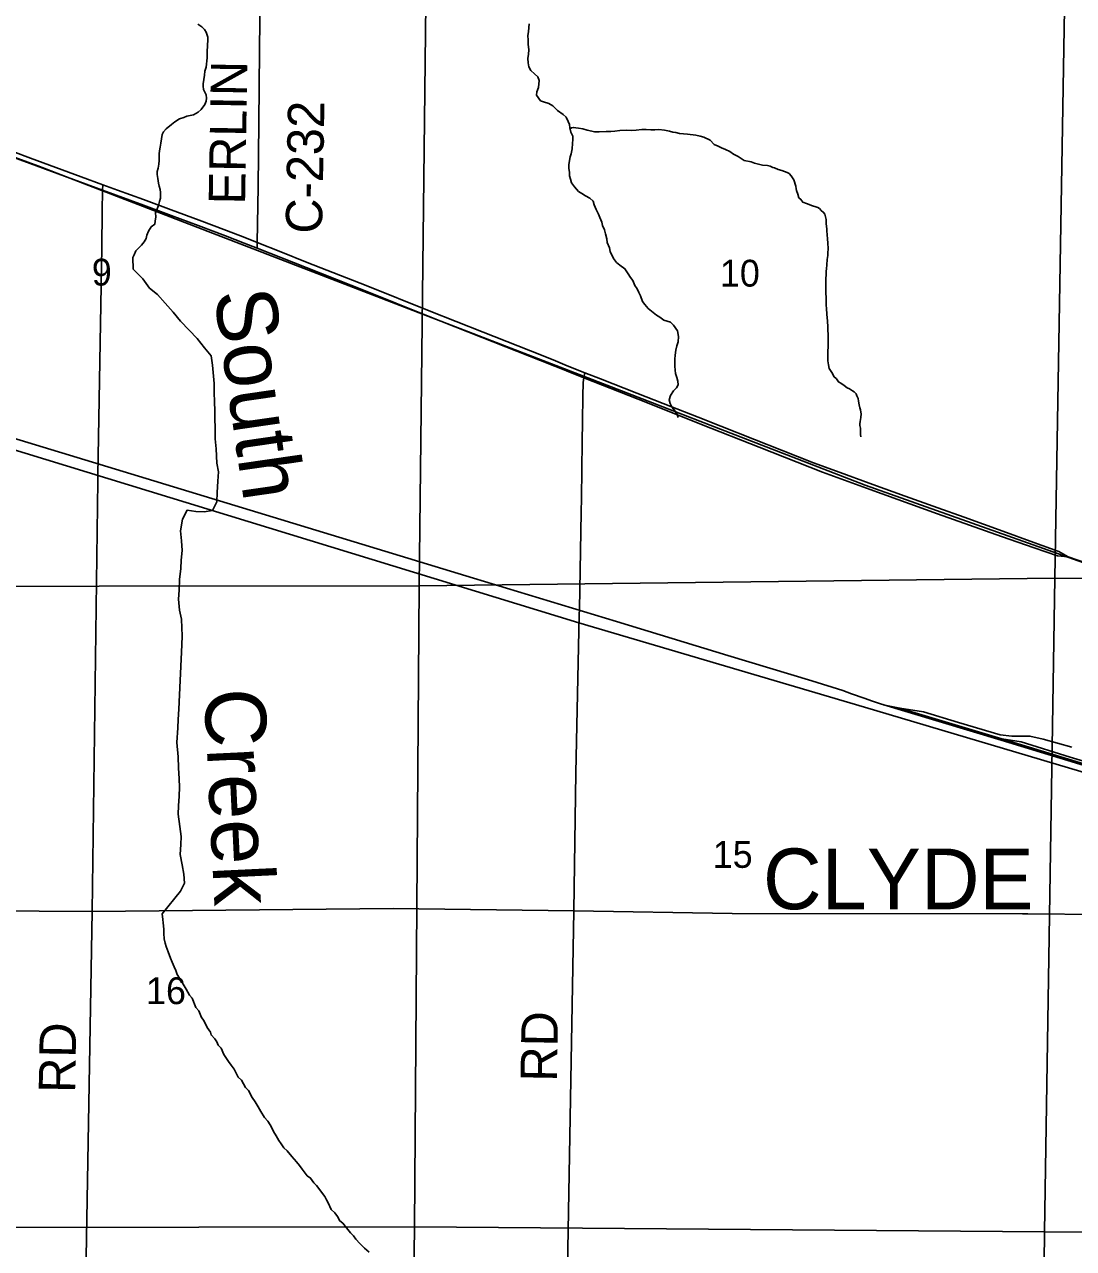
# Model space of a CAD drawing. Extents: x 0 to 34, y 0 to 22.
# Drawn here: x 4.9 to 6.537, y 17.423 to 19.332 of the extents above; entities that cross this region are included whole.
import ezdxf

# ---------------------------------------------------------------- set-up
doc = ezdxf.new("R2010")
doc.units = 0
for name, color, linetype in [('GM_X_Corporation_Text', 7, 'Continuous'), ('GM_X_County_Road', 7, 'Continuous'), ('GM_X_County_Road_Text', 7, 'Continuous'), ('GM_X_Minor_River', 7, 'Continuous'), ('GM_X_Minor_River_Text', 7, 'Continuous'), ('GM_X_Rail_Line', 7, 'Continuous'), ('GM_X_Section', 7, 'Continuous'), ('GM_X_Section_Text', 7, 'Continuous'), ('GM_X_Township_Road', 7, 'Continuous'), ('GM_X_Township_Road_Text', 7, 'Continuous'), ('GM_X_US_Route', 7, 'Continuous')]:
    doc.layers.add(name, color=color, linetype=linetype)

msp = doc.modelspace()

# ---------------------------------------------------------------- linework, layer by layer
at = {"layer": 'GM_X_County_Road'}
msp.add_line((6.4655, 17.9453), (6.6276, 17.9439), dxfattribs=at)
for points in [[(5.2631, 18.9836), (5.2634, 18.9924), (5.2647, 19.0793), (5.2659, 19.1795), (5.2671, 19.291), (5.2679, 19.3886), (5.2681, 19.4561), (5.2767, 19.9672)], [(4.5096, 17.9519), (5.0061, 17.9488), (5.4754, 17.9533), (5.7574, 17.9498)], [(5.7574, 17.9498), (6.0046, 17.9455), (6.4574, 17.9454), (6.4655, 17.9453)]]:
    msp.add_lwpolyline(points, dxfattribs=at)
at = {"layer": 'GM_X_Minor_River'}
for points in [[(5.1708, 19.3327), (5.1768, 19.3289), (5.1813, 19.3246), (5.1836, 19.3204), (5.1861, 19.3128), (5.1864, 19.3071), (5.186, 19.3011), (5.1855, 19.2882), (5.1854, 19.2802), (5.1837, 19.2658), (5.1817, 19.2594), (5.1809, 19.2533), (5.1788, 19.24), (5.1788, 19.2359), (5.1795, 19.2309), (5.1817, 19.2267), (5.1836, 19.2225), (5.1843, 19.2172), (5.1838, 19.2126), (5.1815, 19.2074), (5.1757, 19.1998), (5.1715, 19.1957), (5.1642, 19.1916), (5.1536, 19.1891), (5.149, 19.1872), (5.1422, 19.1854), (5.1349, 19.1805), (5.1296, 19.1764), (5.1211, 19.1697), (5.1173, 19.1648), (5.1153, 19.1606), (5.1129, 19.147), (5.1117, 19.1409), (5.1109, 19.1352), (5.1104, 19.1307), (5.1103, 19.1204), (5.1099, 19.1144), (5.1087, 19.1083), (5.1075, 19.103), (5.1074, 19.0985), (5.1081, 19.092), (5.1095, 19.0848)], [(5.6878, 19.3333), (5.6874, 19.3276), (5.6866, 19.3211), (5.6857, 19.3151), (5.686, 19.3078), (5.6863, 19.3014), (5.687, 19.2926), (5.6865, 19.2858), (5.6857, 19.2794), (5.686, 19.2725), (5.6874, 19.2661), (5.6904, 19.2607), (5.696, 19.2554), (5.7013, 19.2507), (5.7035, 19.245), (5.7023, 19.234), (5.6995, 19.2272), (5.6991, 19.2219), (5.7054, 19.2131), (5.7103, 19.2115), (5.7183, 19.2092), (5.7247, 19.2053), (5.7318, 19.1984), (5.7405, 19.1922), (5.7453, 19.1876), (5.7487, 19.1812), (5.7505, 19.1762), (5.7512, 19.1709), (5.7527, 19.1644), (5.7556, 19.1579), (5.7559, 19.153), (5.7555, 19.1465), (5.7546, 19.1382), (5.7534, 19.1306), (5.7518, 19.1257), (5.7506, 19.1204), (5.7498, 19.1136), (5.7497, 19.1083), (5.7504, 19.1014)], [(5.7515, 19.1696), (5.7538, 19.1713), (5.7564, 19.1717), (5.7606, 19.1709), (5.7644, 19.1706), (5.7716, 19.1694), (5.7781, 19.1676), (5.7853, 19.1661), (5.7895, 19.165), (5.7971, 19.165), (5.8077, 19.1654), (5.8149, 19.1655), (5.8214, 19.1659), (5.829, 19.1671), (5.8388, 19.1675), (5.8472, 19.1668), (5.8544, 19.1676), (5.8635, 19.1684), (5.87, 19.1688), (5.8776, 19.1681), (5.884, 19.1681), (5.8901, 19.1685), (5.8988, 19.1674), (5.9068, 19.1659), (5.9117, 19.1644), (5.9163, 19.1637), (5.9224, 19.1622), (5.9345, 19.1611), (5.9478, 19.1597), (5.9543, 19.1582), (5.9604, 19.1567), (5.9703, 19.1518), (5.9764, 19.1454), (5.9828, 19.1427), (5.9878, 19.1397), (5.9942, 19.1375), (6.0007, 19.1341), (6.0064, 19.1299), (6.0137, 19.1265), (6.0232, 19.1201), (6.0338, 19.1179), (6.0395, 19.116), (6.0517, 19.1131), (6.0597, 19.1123), (6.0635, 19.1112), (6.068, 19.1093), (6.0707, 19.109), (6.0764, 19.106), (6.0821, 19.1045), (6.0863, 19.103), (6.0901, 19.1015), (6.0931, 19.1), (6.0962, 19.0962), (6.1004, 19.0901), (6.1035, 19.0799), (6.1043, 19.0761), (6.105, 19.0734), (6.1066, 19.0677), (6.1085, 19.062), (6.1116, 19.0594), (6.1146, 19.0552), (6.1203, 19.053), (6.1298, 19.0496), (6.1348, 19.0477), (6.1378, 19.047), (6.1405, 19.0451), (6.1435, 19.0421), (6.147, 19.0391), (6.1492, 19.0364), (6.1512, 19.0281), (6.1512, 19.0212), (6.152, 19.0136), (6.152, 19.0102), (6.1528, 19.0049), (6.1532, 18.9973), (6.1536, 18.9916), (6.1541, 18.9825), (6.1537, 18.976), (6.1534, 18.9719), (6.1526, 18.9658), (6.1523, 18.9574), (6.1516, 18.951), (6.1512, 18.9475), (6.1508, 18.9445), (6.1505, 18.9335), (6.1506, 18.9122), (6.151, 18.9077), (6.1511, 18.8944), (6.1515, 18.8891), (6.1519, 18.8807), (6.1527, 18.8746), (6.1531, 18.8701), (6.1531, 18.8674), (6.1535, 18.8629), (6.1539, 18.8545), (6.154, 18.8496), (6.1544, 18.8439), (6.154, 18.8404), (6.1541, 18.831), (6.1541, 18.8275), (6.1537, 18.8249)], [(5.7504, 19.1014), (5.7507, 19.0961), (5.7522, 19.0912), (5.7536, 19.0851), (5.7585, 19.0793), (5.7649, 19.072), (5.7698, 19.0686), (5.7758, 19.0651), (5.7822, 19.0612), (5.7875, 19.0566), (5.7893, 19.0509), (5.7922, 19.0437), (5.7956, 19.0364), (5.7978, 19.0315), (5.8011, 19.0238), (5.8022, 19.0189), (5.8052, 19.012), (5.8066, 19.0059), (5.8088, 18.9979), (5.8095, 18.9922), (5.8128, 18.9838), (5.8143, 18.9781), (5.8191, 18.9671), (5.8239, 18.9613), (5.8292, 18.9567), (5.8371, 18.9513), (5.8423, 18.9433), (5.846, 18.9379), (5.8494, 18.933), (5.8523, 18.9253), (5.8561, 18.92), (5.8587, 18.9143), (5.8616, 18.9093), (5.8646, 18.9005), (5.8679, 18.8956), (5.8735, 18.8894), (5.8788, 18.8852), (5.8863, 18.8791), (5.8916, 18.876), (5.8976, 18.8713), (5.9029, 18.8694), (5.9082, 18.8678), (5.9131, 18.8632), (5.919, 18.8544), (5.9205, 18.8457), (5.92, 18.8373), (5.918, 18.8309), (5.9164, 18.8245), (5.9156, 18.8165), (5.9147, 18.8101), (5.9147, 18.8047), (5.915, 18.7994), (5.9153, 18.793), (5.916, 18.788), (5.9182, 18.7816), (5.9197, 18.7758), (5.9204, 18.7705), (5.9173, 18.7656), (5.9127, 18.7607), (5.9084, 18.7539), (5.906, 18.7468), (5.9075, 18.7411), (5.9108, 18.7349), (5.9157, 18.7292), (5.9187, 18.7242), (5.9201, 18.7193)], [(5.1095, 19.0848), (5.1106, 19.0802), (5.1117, 19.0749), (5.1124, 19.0703), (5.1123, 19.0612), (5.1111, 19.0563), (5.1091, 19.0499), (5.1072, 19.0446), (5.1045, 19.0385), (5.1051, 19.0321), (5.1043, 19.0256), (5.1035, 19.0207), (5.0978, 19.0166), (5.0935, 19.0102), (5.0912, 19.0037), (5.09, 18.9984), (5.0872, 18.9935), (5.0826, 18.9883), (5.0788, 18.9841), (5.0738, 18.9793), (5.0715, 18.9732), (5.0692, 18.9689)], [(5.0692, 18.9689), (5.0697, 18.9508), (5.0851, 18.9355), (5.0955, 18.9209), (5.1079, 18.9113), (5.1199, 18.8979), (5.1323, 18.8837), (5.1439, 18.8696), (5.157, 18.8558), (5.1697, 18.8423), (5.1809, 18.8282), (5.1914, 18.8155), (5.1935, 18.8011), (5.1962, 18.7722), (5.1961, 18.7586), (5.1967, 18.743), (5.1973, 18.7301), (5.1975, 18.7172), (5.1977, 18.7031), (5.1979, 18.686), (5.1992, 18.6705), (5.2005, 18.6481), (5.203, 18.6344), (5.2021, 18.62), (5.2007, 18.6021), (5.2002, 18.5877), (5.1936, 18.5745), (5.1807, 18.5724), (5.1678, 18.5729), (5.1541, 18.5749), (5.1468, 18.5606), (5.1439, 18.5428), (5.1452, 18.5272), (5.1462, 18.512), (5.1449, 18.4968), (5.144, 18.4839), (5.1423, 18.4665), (5.1417, 18.4498), (5.1408, 18.4358), (5.1421, 18.4187), (5.145, 18.405), (5.146, 18.3913), (5.1462, 18.3788), (5.1456, 18.3647), (5.1411, 18.2642), (5.1401, 18.2483), (5.1396, 18.2354), (5.1378, 18.2122), (5.1402, 18.1902), (5.1408, 18.1731), (5.1417, 18.1557), (5.142, 18.1427), (5.1418, 18.1287), (5.1405, 18.1135), (5.14, 18.1006), (5.1428, 18.0812), (5.1445, 18.066), (5.1443, 18.0535), (5.143, 18.0376), (5.1463, 18.0216), (5.1491, 18.0072), (5.1501, 17.9931), (5.1439, 17.9807), (5.1151, 17.9449)], [(6.1537, 18.8249), (6.1534, 18.8161), (6.1534, 18.8104), (6.1538, 18.8078), (6.1546, 18.8017), (6.1558, 18.796), (6.1577, 18.7926), (6.1607, 18.7881), (6.163, 18.7831), (6.1672, 18.7794), (6.1703, 18.7748), (6.1741, 18.7729), (6.179, 18.7695), (6.184, 18.7654), (6.1874, 18.7643), (6.192, 18.7609), (6.195, 18.7594), (6.1981, 18.7563), (6.1989, 18.7533), (6.2012, 18.7488), (6.2016, 18.7446), (6.2027, 18.7393), (6.2035, 18.7343), (6.2047, 18.7313), (6.2051, 18.7279), (6.2055, 18.7252), (6.2051, 18.7195), (6.204, 18.7131), (6.2036, 18.7096), (6.2036, 18.707), (6.2044, 18.7028), (6.2048, 18.7002), (6.2048, 18.6967), (6.2045, 18.6929), (6.2049, 18.6891)], [(5.115, 17.9453), (5.1161, 17.9362), (5.1168, 17.9312), (5.1178, 17.921), (5.1177, 17.9145), (5.1184, 17.9062), (5.1198, 17.8993), (5.1213, 17.894), (5.1242, 17.886), (5.1283, 17.8761), (5.1309, 17.8696), (5.1338, 17.8623), (5.1364, 17.8566), (5.1386, 17.8505), (5.1434, 17.8433), (5.1479, 17.8352), (5.1524, 17.8276), (5.1576, 17.8184), (5.1617, 17.8138), (5.1676, 17.7993), (5.1721, 17.794), (5.1765, 17.7833), (5.1803, 17.7787), (5.1851, 17.768), (5.1907, 17.7608), (5.1914, 17.7562), (5.197, 17.7501), (5.2004, 17.7455), (5.2026, 17.7401), (5.2071, 17.7355), (5.2111, 17.7256), (5.2156, 17.7195), (5.2186, 17.7149), (5.2227, 17.7092), (5.2272, 17.7031), (5.2339, 17.6905), (5.2391, 17.6855), (5.2451, 17.6744), (5.2499, 17.6694), (5.2555, 17.6587), (5.2604, 17.6518), (5.2648, 17.6442), (5.2689, 17.6369), (5.2745, 17.6274), (5.2797, 17.622), (5.2838, 17.6159), (5.2861, 17.6113), (5.289, 17.6056), (5.2931, 17.5991), (5.2972, 17.5918), (5.301, 17.5865), (5.3047, 17.58), (5.3103, 17.5754), (5.3174, 17.5666), (5.3245, 17.5581), (5.3294, 17.5524), (5.3335, 17.547), (5.3414, 17.5367), (5.3466, 17.5329), (5.3515, 17.5256), (5.356, 17.5214), (5.3597, 17.5168), (5.3653, 17.5091), (5.3687, 17.5042), (5.3717, 17.4992), (5.3739, 17.4942), (5.3787, 17.4839), (5.3847, 17.4786), (5.3888, 17.4728), (5.3921, 17.4663), (5.397, 17.4625), (5.4026, 17.4552), (5.409, 17.4475), (5.4135, 17.4429), (5.4172, 17.4376), (5.4236, 17.4311), (5.4307, 17.4238), (5.4379, 17.4176)]]:
    msp.add_lwpolyline(points, dxfattribs=at)
at = {"layer": 'GM_X_Rail_Line'}
msp.add_line((6.2402, 18.2714), (6.2658, 18.2658), dxfattribs=at)
for points in [[(2.1, 20.1355), (2.5574, 19.9667), (3.1422, 19.7506), (3.6996, 19.5506), (4.3507, 19.3207), (4.9212, 19.1118), (5.8157, 18.7674), (6.212, 18.6139), (6.6644, 18.4531), (7.3247, 18.2205), (7.6757, 18.0934)], [(2.1, 19.5186), (2.8346, 19.2964), (3.6748, 19.0394), (4.5141, 18.7823), (5.7652, 18.3991), (6.2109, 18.2673), (6.7654, 18.1025), (7.4524, 17.8921)], [(4.5185, 18.7976), (5.0181, 18.6458), (5.6006, 18.4688), (5.8239, 18.4011), (5.9978, 18.3483), (6.1287, 18.3087), (6.1769, 18.2935), (6.1907, 18.2885), (6.2103, 18.2813), (6.2231, 18.2768), (6.2357, 18.2728), (6.4243, 18.2159), (6.6203, 18.1561)], [(6.2658, 18.2658), (6.2693, 18.2651), (6.425, 18.2181)], [(6.2658, 18.2658), (6.303, 18.2603), (6.3573, 18.2434), (6.4225, 18.2245), (6.4407, 18.2223), (6.4689, 18.2224), (6.4896, 18.2174), (6.5344, 18.2051)], [(6.718, 18.1294), (6.6742, 18.1467), (6.5315, 18.1897), (6.4552, 18.2136), (6.425, 18.2181)], [(6.425, 18.2181), (6.621, 18.1583), (6.7057, 18.1327), (6.718, 18.1294)]]:
    msp.add_lwpolyline(points, dxfattribs=at)
at = {"layer": 'GM_X_Section'}
for points in [[(5.5276, 19.4562), (5.5161, 18.4568), (4.517, 18.4555), (4.5252, 19.4639)], [(6.5246, 19.4487), (6.5078, 18.4687), (5.5161, 18.4568), (5.5276, 19.4562)], [(6.5246, 19.4487), (7.5241, 19.4466), (7.5189, 18.4589), (6.5078, 18.4687)], [(6.5078, 18.4687), (6.4919, 17.4489), (5.5087, 17.4571), (5.5161, 18.4568)], [(7.5189, 18.4589), (7.5107, 17.4428), (6.4919, 17.4489), (6.5078, 18.4687)], [(5.5161, 18.4568), (5.5087, 17.4571), (4.4991, 17.4554), (4.517, 18.4555)], [(5.5087, 17.4571), (5.4956, 16.4418), (4.4826, 16.453), (4.4991, 17.4554)], [(6.4919, 17.4489), (6.481, 16.4419), (5.4956, 16.4418), (5.5087, 17.4571)], [(6.4919, 17.4489), (7.5107, 17.4428), (7.4967, 16.4401), (6.481, 16.4419)]]:
    msp.add_lwpolyline(points, close=True, dxfattribs=at)
at = {"layer": 'GM_X_Township_Road'}
for p, q in [((5.766, 18.4209), (5.7687, 18.5709)), ((4.9885, 16.9486), (5.0061, 17.9488))]:
    msp.add_line(p, q, dxfattribs=at)
for points in [[(5.0207, 18.9851), (5.0214, 19.0407), (5.0221, 19.0739), (5.0227, 19.0824)], [(5.0148, 18.6294), (5.0203, 18.9543), (5.0207, 18.9851)], [(5.7702, 18.6812), (5.7707, 18.7133), (5.7713, 18.7524), (5.7721, 18.7738), (5.7728, 18.7811), (5.7743, 18.7892)], [(5.7687, 18.5709), (5.7691, 18.5939), (5.7702, 18.6812)], [(5.0061, 17.9488), (5.0146, 18.6205), (5.0148, 18.6294)], [(5.7395, 16.953), (5.7574, 17.9498), (5.7604, 18.1653), (5.7658, 18.4109), (5.766, 18.4209)]]:
    msp.add_lwpolyline(points, dxfattribs=at)
at = {"layer": 'GM_X_US_Route'}
for points in [[(4.5214, 19.2666), (4.5628, 19.2515), (4.6116, 19.2335), (4.7056, 19.199), (4.7477, 19.1835), (4.805, 19.1625), (4.8542, 19.1444), (4.9095, 19.124), (4.9887, 19.0949), (5.0227, 19.0824), (5.0456, 19.0741), (5.0862, 19.0592), (5.1293, 19.0433), (5.1729, 19.0273), (5.2156, 19.0112), (5.244, 19), (5.2634, 18.9924), (5.3001, 18.9779), (5.3415, 18.9613), (5.4332, 18.9251), (5.5318, 18.8857), (5.6159, 18.8525), (5.7071, 18.8163), (5.729, 18.8075)], [(4.5213, 19.2577), (4.611, 19.225), (4.7241, 19.1834), (4.8167, 19.1493), (4.9089, 19.1155), (4.9868, 19.0868), (5.0221, 19.0739), (5.0434, 19.0662), (5.0859, 19.0504), (5.129, 19.0346), (5.1712, 19.0188), (5.2139, 19.0026), (5.243, 18.9914), (5.2631, 18.9836), (5.34, 18.9532), (5.4317, 18.9169), (5.5303, 18.8776), (5.6144, 18.8443), (5.7056, 18.8082), (5.7275, 18.7993)], [(5.729, 18.8075), (5.7472, 18.8001), (5.7743, 18.7892)], [(5.7275, 18.7993), (5.7457, 18.792), (5.7728, 18.7811), (5.8577, 18.7479), (5.867, 18.7442)], [(5.7743, 18.7892), (5.7992, 18.7796), (5.8554, 18.7573), (5.8965, 18.741), (5.9513, 18.7196), (5.9867, 18.7057), (6.0392, 18.6852), (6.0816, 18.6683), (6.1314, 18.6488), (6.167, 18.6355), (6.224, 18.6147), (6.2741, 18.5968), (6.3255, 18.5782), (6.3665, 18.5637), (6.4267, 18.542), (6.4753, 18.5245), (6.5143, 18.5105), (6.5287, 18.5018)], [(5.867, 18.7442), (5.9565, 18.7086), (6.0464, 18.673), (6.1454, 18.6343), (6.2197, 18.6069), (6.3248, 18.569), (6.4246, 18.5338), (6.4754, 18.5158), (6.5122, 18.5033), (6.5287, 18.5018)], [(6.5287, 18.5018), (6.6127, 18.4729), (6.7072, 18.4402), (6.7709, 18.4179), (6.7993, 18.4076)]]:
    msp.add_lwpolyline(points, dxfattribs=at)

# ---------------------------------------------------------------- texts
at = {"layer": 'GM_X_Corporation_Text'}
msp.add_text('CLYDE', height=0.0947, rotation=0, dxfattribs=at).set_placement((6.0525, 17.9523))
at = {"layer": 'GM_X_County_Road_Text'}
for s, rotation, p in [('ERLIN', 89.0651, (5.2444, 19.0513)), ('C-232', 88.8978, (5.3644, 19.0057))]:
    msp.add_text(s, height=0.05682, rotation=rotation, dxfattribs=at).set_placement(p)
at = {"layer": 'GM_X_Minor_River_Text'}
for s, rotation, p in [('South', 278.2239, (5.1955, 18.914)), ('Creek', 272.7558, (5.1804, 18.2947))]:
    msp.add_text(s, height=0.09474, rotation=rotation, dxfattribs=at).set_placement(p)
at = {"layer": 'GM_X_Section_Text'}
for s, height, p in [('9', 0.0419, (5.0053, 18.9251)), ('10', 0.04186, (5.9853, 18.9235)), ('15', 0.04186, (5.9741, 18.0169)), ('16', 0.04186, (5.0899, 17.8043))]:
    msp.add_text(s, height=height, rotation=0, dxfattribs=at).set_placement(p)
at = {"layer": 'GM_X_Township_Road_Text'}
for p in [(5.7309, 17.683), (4.9792, 17.6655)]:
    msp.add_text('RD', height=0.05682, rotation=89.0128, dxfattribs=at).set_placement(p)

doc.saveas('drawing.dxf')
